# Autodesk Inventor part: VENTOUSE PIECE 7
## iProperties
Created: 2004-11
Part Number: VENTOUSE PIECE 7
Document SubType Name: Modeling
Designer: Bruno
Manufacturer: Standard
Standards Organization: Custom
Author: Bruno
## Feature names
1. Base1
